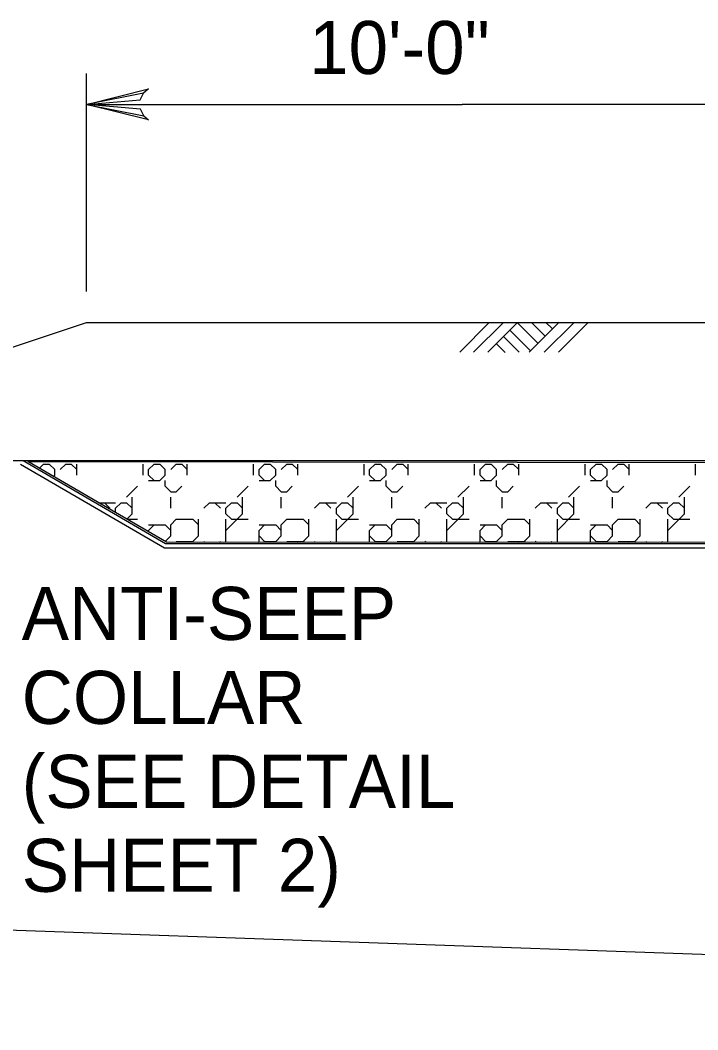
# Model space of a CAD drawing. Extents: x 636462 to 639890, y 299944 to 300538.
# Drawn here: x 638419.8 to 638458.1, y 300127.4 to 300184.4 of the extents above; entities that cross this region are included whole.
import ezdxf

# ---------------------------------------------------------------- set-up
doc = ezdxf.new("R2010")
doc.units = 0
doc.layers.add('Default', color=7, linetype='Continuous')

msp = doc.modelspace()

# ---------------------------------------------------------------- linework, layer by layer
at = {"layer": 'Default'}
for p, q in [((638423.521, 300169.088), (638423.521, 300181.405)), ((638423.521, 300179.656), (638444.757, 300179.656)), ((638465.993, 300179.656), (638444.757, 300179.656)), ((638444.613, 300165.657), (638446.285, 300167.331)), ((638445.396, 300165.657), (638447.078, 300167.339)), ((638446.204, 300165.657), (638447.886, 300167.339)), ((638447.851, 300167.339), (638449.038, 300166.152)), ((638448.534, 300165.657), (638450.226, 300167.348)), ((638448.661, 300167.339), (638449.433, 300166.565)), ((638449.389, 300165.657), (638451.053, 300167.32)), ((638449.479, 300167.339), (638449.848, 300166.971)), ((638450.199, 300165.657), (638451.863, 300167.32)), ((638447.447, 300166.898), (638448.607, 300165.738)), ((638446.681, 300166.134), (638447.185, 300165.63)), ((638447.087, 300166.54), (638447.967, 300165.657)), ((638419.931, 300159.532), (638427.979, 300154.847)), ((638420.466, 300159.321), (638420.466, 300159.332)), ((638420.854, 300159.095), (638421.09, 300159.332)), ((638421.09, 300159.332), (638421.403, 300159.332)), ((638421.715, 300159.019), (638421.403, 300159.332)), ((638422.027, 300159.019), (638422.34, 300159.332)), ((638422.34, 300159.332), (638422.652, 300159.332)), ((638422.964, 300159.019), (638422.652, 300159.332)), ((638422.964, 300158.707), (638422.964, 300159.332)), ((638426.712, 300158.707), (638426.712, 300159.332)), ((638427.024, 300159.019), (638427.336, 300159.332)), ((638427.336, 300159.332), (638427.649, 300159.332)), ((638427.961, 300159.019), (638427.649, 300159.332)), ((638428.273, 300159.019), (638428.585, 300159.332)), ((638428.585, 300159.332), (638428.898, 300159.332)), ((638429.21, 300159.019), (638428.898, 300159.332)), ((638429.21, 300158.707), (638429.21, 300159.332)), ((638432.958, 300158.707), (638432.958, 300159.332)), ((638433.27, 300159.019), (638433.582, 300159.332)), ((638433.582, 300159.332), (638433.895, 300159.332)), ((638434.207, 300159.019), (638433.895, 300159.332)), ((638434.519, 300159.019), (638434.831, 300159.332)), ((638434.831, 300159.332), (638435.144, 300159.332)), ((638435.456, 300159.019), (638435.144, 300159.332)), ((638435.456, 300158.707), (638435.456, 300159.332)), ((638439.204, 300158.707), (638439.204, 300159.332)), ((638439.516, 300159.019), (638439.828, 300159.332)), ((638439.828, 300159.332), (638440.14, 300159.332)), ((638440.453, 300159.019), (638440.14, 300159.332)), ((638440.765, 300159.019), (638441.077, 300159.332)), ((638441.077, 300159.332), (638441.39, 300159.332)), ((638441.702, 300159.019), (638441.39, 300159.332)), ((638441.702, 300158.707), (638441.702, 300159.332)), ((638445.449, 300158.707), (638445.449, 300159.332)), ((638445.762, 300159.019), (638446.074, 300159.332)), ((638446.074, 300159.332), (638446.386, 300159.332)), ((638446.699, 300159.019), (638446.386, 300159.332)), ((638447.011, 300159.019), (638447.323, 300159.332)), ((638447.323, 300159.332), (638447.636, 300159.332)), ((638447.948, 300159.019), (638447.636, 300159.332)), ((638447.948, 300158.707), (638447.948, 300159.332)), ((638451.695, 300158.707), (638451.695, 300159.332)), ((638452.008, 300159.019), (638452.32, 300159.332)), ((638452.32, 300159.332), (638452.632, 300159.332)), ((638452.945, 300159.019), (638452.632, 300159.332)), ((638453.257, 300159.019), (638453.569, 300159.332)), ((638453.569, 300159.332), (638453.881, 300159.332)), ((638454.194, 300159.019), (638453.881, 300159.332)), ((638454.194, 300158.707), (638454.194, 300159.332)), ((638457.941, 300158.707), (638457.941, 300159.332)), ((638421.643, 300158.635), (638421.715, 300158.707)), ((638421.715, 300158.707), (638421.715, 300159.019)), ((638427.024, 300158.707), (638427.024, 300159.019)), ((638427.336, 300158.395), (638427.024, 300158.707)), ((638427.649, 300158.395), (638427.961, 300158.707)), ((638427.961, 300158.707), (638427.961, 300159.019)), ((638433.27, 300158.707), (638433.27, 300159.019)), ((638433.582, 300158.395), (638433.27, 300158.707)), ((638433.895, 300158.395), (638434.207, 300158.707)), ((638434.207, 300158.707), (638434.207, 300159.019)), ((638439.516, 300158.707), (638439.516, 300159.019)), ((638439.828, 300158.395), (638439.516, 300158.707)), ((638440.14, 300158.395), (638440.453, 300158.707)), ((638440.453, 300158.707), (638440.453, 300159.019)), ((638445.762, 300158.707), (638445.762, 300159.019)), ((638446.074, 300158.395), (638445.762, 300158.707)), ((638446.386, 300158.395), (638446.699, 300158.707)), ((638446.699, 300158.707), (638446.699, 300159.019)), ((638452.008, 300158.707), (638452.008, 300159.019)), ((638452.32, 300158.395), (638452.008, 300158.707)), ((638452.632, 300158.395), (638452.945, 300158.707)), ((638452.945, 300158.707), (638452.945, 300159.019)), ((638427.024, 300158.395), (638427.649, 300158.395)), ((638427.961, 300158.082), (638427.961, 300158.395)), ((638433.27, 300158.395), (638433.895, 300158.395)), ((638434.207, 300158.082), (638434.207, 300158.395)), ((638439.516, 300158.395), (638440.14, 300158.395)), ((638440.453, 300158.082), (638440.453, 300158.395)), ((638445.762, 300158.395), (638446.386, 300158.395)), ((638446.699, 300158.082), (638446.699, 300158.395)), ((638452.008, 300158.395), (638452.632, 300158.395)), ((638452.945, 300158.082), (638452.945, 300158.395)), ((638422.63, 300158.06), (638422.652, 300158.082)), ((638425.775, 300157.458), (638426.399, 300158.082)), ((638428.273, 300157.77), (638427.961, 300158.082)), ((638428.273, 300157.77), (638428.585, 300157.77)), ((638428.585, 300157.77), (638428.898, 300158.082)), ((638432.021, 300157.458), (638432.645, 300158.082)), ((638434.519, 300157.77), (638434.207, 300158.082)), ((638434.519, 300157.77), (638434.831, 300157.77)), ((638434.831, 300157.77), (638435.144, 300158.082)), ((638438.267, 300157.458), (638438.891, 300158.082)), ((638440.765, 300157.77), (638440.453, 300158.082)), ((638440.765, 300157.77), (638441.077, 300157.77)), ((638441.077, 300157.77), (638441.39, 300158.082)), ((638444.513, 300157.458), (638445.137, 300158.082)), ((638447.011, 300157.77), (638446.699, 300158.082)), ((638447.011, 300157.77), (638447.323, 300157.77)), ((638447.323, 300157.77), (638447.636, 300158.082)), ((638450.759, 300157.458), (638451.383, 300158.082)), ((638453.257, 300157.77), (638452.945, 300158.082)), ((638453.257, 300157.77), (638453.569, 300157.77)), ((638453.569, 300157.77), (638453.881, 300158.082)), ((638457.004, 300157.458), (638457.629, 300158.082)), ((638424.208, 300157.141), (638424.213, 300157.146)), ((638424.213, 300157.146), (638425.15, 300157.146)), ((638424.838, 300156.833), (638424.526, 300157.146)), ((638425.15, 300156.833), (638425.463, 300157.146)), ((638425.463, 300157.146), (638425.775, 300157.146)), ((638426.087, 300156.833), (638425.775, 300157.146)), ((638426.087, 300156.521), (638426.087, 300157.458)), ((638428.273, 300156.833), (638428.273, 300157.458)), ((638430.147, 300156.833), (638430.459, 300157.146)), ((638430.459, 300157.146), (638431.396, 300157.146)), ((638431.084, 300156.833), (638430.772, 300157.146)), ((638431.396, 300156.833), (638431.708, 300157.146)), ((638431.708, 300157.146), (638432.021, 300157.146)), ((638432.333, 300156.833), (638432.021, 300157.146)), ((638432.333, 300156.521), (638432.333, 300157.458)), ((638434.519, 300156.833), (638434.519, 300157.458)), ((638436.393, 300156.833), (638436.705, 300157.146)), ((638436.705, 300157.146), (638437.642, 300157.146)), ((638437.33, 300156.833), (638437.017, 300157.146)), ((638437.642, 300156.833), (638437.954, 300157.146)), ((638437.954, 300157.146), (638438.267, 300157.146)), ((638438.579, 300156.833), (638438.267, 300157.146)), ((638438.579, 300156.521), (638438.579, 300157.458)), ((638440.765, 300156.833), (638440.765, 300157.458)), ((638442.639, 300156.833), (638442.951, 300157.146)), ((638442.951, 300157.146), (638443.888, 300157.146)), ((638443.576, 300156.833), (638443.263, 300157.146)), ((638443.888, 300156.833), (638444.2, 300157.146)), ((638444.2, 300157.146), (638444.513, 300157.146)), ((638444.825, 300156.833), (638444.513, 300157.146)), ((638444.825, 300156.521), (638444.825, 300157.458)), ((638447.011, 300156.833), (638447.011, 300157.458)), ((638448.885, 300156.833), (638449.197, 300157.146)), ((638449.197, 300157.146), (638450.134, 300157.146)), ((638449.822, 300156.833), (638449.509, 300157.146)), ((638450.134, 300156.833), (638450.446, 300157.146)), ((638450.446, 300157.146), (638450.759, 300157.146)), ((638451.071, 300156.833), (638450.759, 300157.146)), ((638451.071, 300156.521), (638451.071, 300157.458)), ((638453.257, 300156.833), (638453.257, 300157.458)), ((638455.131, 300156.833), (638455.443, 300157.146)), ((638455.443, 300157.146), (638456.38, 300157.146)), ((638456.068, 300156.833), (638455.755, 300157.146)), ((638456.38, 300156.833), (638456.692, 300157.146)), ((638456.692, 300157.146), (638457.004, 300157.146)), ((638457.317, 300156.833), (638457.004, 300157.146)), ((638457.317, 300156.521), (638457.317, 300157.458)), ((638425.15, 300156.592), (638425.15, 300156.833)), ((638425.787, 300156.221), (638426.087, 300156.521)), ((638431.396, 300156.521), (638431.396, 300156.833)), ((638431.708, 300156.209), (638431.396, 300156.521)), ((638431.396, 300155.584), (638432.333, 300156.521)), ((638437.642, 300156.521), (638437.642, 300156.833)), ((638437.954, 300156.209), (638437.642, 300156.521)), ((638437.642, 300155.584), (638438.579, 300156.521)), ((638443.888, 300156.521), (638443.888, 300156.833)), ((638444.2, 300156.209), (638443.888, 300156.521)), ((638443.888, 300155.584), (638444.825, 300156.521)), ((638450.134, 300156.521), (638450.134, 300156.833)), ((638450.446, 300156.209), (638450.134, 300156.521)), ((638450.134, 300155.584), (638451.071, 300156.521)), ((638456.38, 300156.521), (638456.38, 300156.833)), ((638456.692, 300156.209), (638456.38, 300156.521)), ((638456.38, 300155.584), (638457.317, 300156.521)), ((638425.807, 300156.209), (638426.399, 300156.209)), ((638427.024, 300155.584), (638427.336, 300155.896)), ((638427.024, 300155.896), (638427.961, 300155.896)), ((638428.273, 300155.584), (638427.961, 300155.896)), ((638428.273, 300155.896), (638428.585, 300156.209)), ((638428.273, 300155.272), (638428.273, 300155.896)), ((638428.585, 300156.209), (638429.522, 300156.209)), ((638429.835, 300155.896), (638429.522, 300156.209)), ((638429.835, 300155.272), (638429.835, 300156.209)), ((638431.396, 300154.96), (638431.396, 300156.209)), ((638431.708, 300156.209), (638432.645, 300156.209)), ((638433.27, 300155.584), (638433.582, 300155.896)), ((638433.27, 300155.896), (638434.207, 300155.896)), ((638434.519, 300155.584), (638434.207, 300155.896)), ((638434.519, 300155.896), (638434.831, 300156.209)), ((638434.519, 300155.272), (638434.519, 300155.896)), ((638434.831, 300156.209), (638435.768, 300156.209)), ((638436.081, 300155.896), (638435.768, 300156.209)), ((638436.081, 300155.272), (638436.081, 300156.209)), ((638437.642, 300154.96), (638437.642, 300156.209)), ((638437.954, 300156.209), (638438.891, 300156.209)), ((638439.516, 300155.584), (638439.828, 300155.896)), ((638439.516, 300155.896), (638440.453, 300155.896)), ((638440.765, 300155.584), (638440.453, 300155.896)), ((638440.765, 300155.896), (638441.077, 300156.209)), ((638440.765, 300155.272), (638440.765, 300155.896)), ((638441.077, 300156.209), (638442.014, 300156.209)), ((638442.327, 300155.896), (638442.014, 300156.209)), ((638442.327, 300155.272), (638442.327, 300156.209)), ((638443.888, 300154.96), (638443.888, 300156.209)), ((638444.2, 300156.209), (638445.137, 300156.209)), ((638445.762, 300155.584), (638446.074, 300155.896)), ((638445.762, 300155.896), (638446.699, 300155.896)), ((638447.011, 300155.584), (638446.699, 300155.896)), ((638447.011, 300155.896), (638447.323, 300156.209)), ((638447.011, 300155.272), (638447.011, 300155.896)), ((638447.323, 300156.209), (638448.26, 300156.209)), ((638448.572, 300155.896), (638448.26, 300156.209)), ((638448.572, 300155.272), (638448.572, 300156.209)), ((638450.134, 300154.96), (638450.134, 300156.209)), ((638450.446, 300156.209), (638451.383, 300156.209)), ((638452.008, 300155.584), (638452.32, 300155.896)), ((638452.008, 300155.896), (638452.945, 300155.896)), ((638453.257, 300155.584), (638452.945, 300155.896)), ((638453.257, 300155.896), (638453.569, 300156.209)), ((638453.257, 300155.272), (638453.257, 300155.896)), ((638453.569, 300156.209), (638454.506, 300156.209)), ((638454.818, 300155.896), (638454.506, 300156.209)), ((638454.818, 300155.272), (638454.818, 300156.209)), ((638456.38, 300154.96), (638456.38, 300156.209)), ((638456.692, 300156.209), (638457.629, 300156.209)), ((638427.024, 300155.5), (638427.024, 300155.584)), ((638427.961, 300154.96), (638428.273, 300155.272)), ((638429.522, 300154.96), (638429.835, 300155.272)), ((638433.27, 300154.96), (638433.27, 300155.584)), ((638433.582, 300154.96), (638433.27, 300155.272)), ((638434.207, 300154.96), (638434.519, 300155.272)), ((638435.768, 300154.96), (638436.081, 300155.272)), ((638439.516, 300154.96), (638439.516, 300155.584)), ((638439.828, 300154.96), (638439.516, 300155.272)), ((638440.453, 300154.96), (638440.765, 300155.272)), ((638442.014, 300154.96), (638442.327, 300155.272)), ((638445.762, 300154.96), (638445.762, 300155.584)), ((638446.074, 300154.96), (638445.762, 300155.272)), ((638446.699, 300154.96), (638447.011, 300155.272)), ((638448.26, 300154.96), (638448.572, 300155.272)), ((638452.008, 300154.96), (638452.008, 300155.584)), ((638452.32, 300154.96), (638452.008, 300155.272)), ((638452.945, 300154.96), (638453.257, 300155.272)), ((638454.506, 300154.96), (638454.818, 300155.272)), ((638427.951, 300154.96), (638427.961, 300154.96)), ((638428.585, 300154.96), (638429.522, 300154.96)), ((638429.165, 300154.915), (638429.21, 300154.96)), ((638429.567, 300154.915), (638429.522, 300154.96)), ((638430.192, 300154.915), (638430.147, 300154.96)), ((638431.039, 300154.914), (638431.084, 300154.96)), ((638433.224, 300154.914), (638433.27, 300154.96)), ((638433.582, 300154.96), (638434.207, 300154.96)), ((638434.831, 300154.96), (638435.768, 300154.96)), ((638435.409, 300154.913), (638435.456, 300154.96)), ((638435.815, 300154.913), (638435.768, 300154.96)), ((638436.44, 300154.913), (638436.393, 300154.96)), ((638437.283, 300154.912), (638437.33, 300154.96)), ((638439.468, 300154.912), (638439.516, 300154.96)), ((638439.828, 300154.96), (638440.453, 300154.96)), ((638441.077, 300154.96), (638442.014, 300154.96)), ((638441.653, 300154.911), (638441.702, 300154.96)), ((638442.063, 300154.911), (638442.014, 300154.96)), ((638442.688, 300154.911), (638442.639, 300154.96)), ((638443.527, 300154.91), (638443.576, 300154.96)), ((638445.712, 300154.91), (638445.762, 300154.96)), ((638446.074, 300154.96), (638446.699, 300154.96)), ((638447.323, 300154.96), (638448.26, 300154.96)), ((638447.897, 300154.909), (638447.948, 300154.96)), ((638448.311, 300154.909), (638448.26, 300154.96)), ((638448.935, 300154.909), (638448.885, 300154.96)), ((638449.771, 300154.909), (638449.822, 300154.96)), ((638451.956, 300154.908), (638452.008, 300154.96)), ((638452.32, 300154.96), (638452.945, 300154.96)), ((638453.569, 300154.96), (638454.506, 300154.96)), ((638454.141, 300154.907), (638454.194, 300154.96)), ((638454.559, 300154.907), (638454.506, 300154.96)), ((638455.183, 300154.907), (638455.131, 300154.96)), ((638456.015, 300154.907), (638456.068, 300154.96)), ((638355.447, 300135.22), (638469.314, 300131.243))]:
    msp.add_line(p, q, dxfattribs=at)
for points in [[(638426.753, 300179.019), (638427.022, 300178.796), (638423.521, 300179.656), (638426.753, 300179.019), (638426.556, 300179.392), (638423.521, 300179.656), (638426.55, 300179.915), (638426.733, 300180.291), (638423.521, 300179.656), (638427.015, 300180.544), (638426.733, 300180.291)], [(638334.334, 300137.61), (638423.521, 300167.339), (638444.757, 300167.339), (638465.993, 300167.339)], [(638400.099, 300159.532), (638444.757, 300159.532), (638489.415, 300159.532)], [(638419.787, 300159.33), (638427.928, 300154.599), (638488.624, 300154.599), (638568.6, 300127.803)], [(638544.627, 300136.331), (638488.696, 300154.897), (638428.027, 300154.915), (638420.199, 300159.477), (638489.373, 300159.381), (638585.285, 300127.352), (638570.051, 300127.892), (638546.379, 300135.75)], [(638427.979, 300154.847), (638444.757, 300154.847), (638488.655, 300154.847), (638544.532, 300136.222)]]:
    msp.add_lwpolyline(points, dxfattribs=at)

# ---------------------------------------------------------------- texts
for s, height, p in [('10\'-0"', 2.998, (638436.099, 300181.381)), ('ANTI-SEEP', 2.998, (638419.85, 300149.392)), ('COLLAR', 2.998, (638419.85, 300144.646)), ('(SEE DETAIL ', 2.99804, (638419.85, 300139.899)), ('SHEET 2)', 2.998, (638419.85, 300135.152))]:
    msp.add_text(s, height=height, dxfattribs=at).set_placement(p)

doc.saveas('drawing.dxf')
